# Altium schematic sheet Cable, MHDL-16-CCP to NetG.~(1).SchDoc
size B
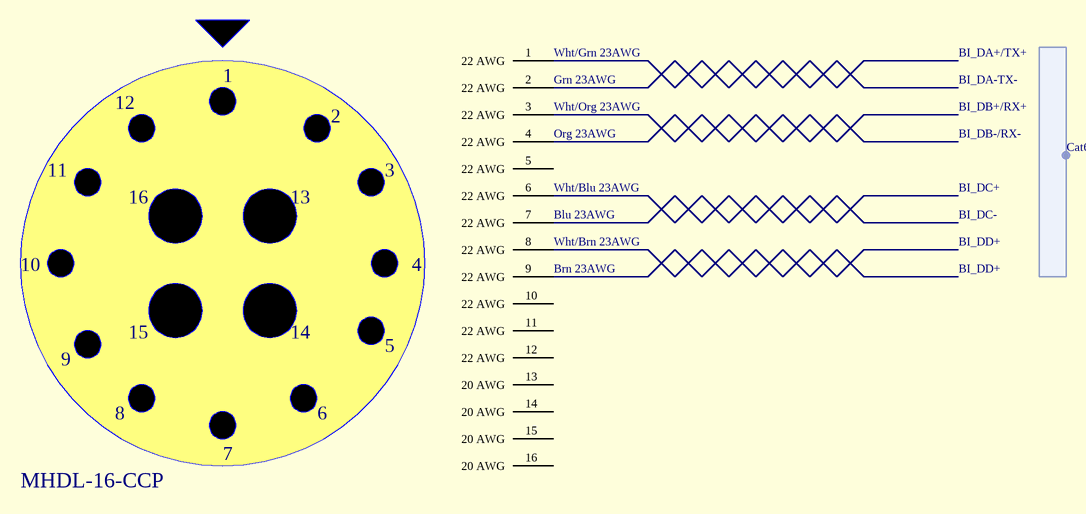
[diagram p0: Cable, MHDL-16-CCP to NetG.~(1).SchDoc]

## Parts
J?  MHDL-16-CCP

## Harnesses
Cat6E wired to TIA/EIA 568A Standard: 

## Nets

Not connected (* = marked no-connect by the designer): J? 1(22_AWG) 2(22_AWG) 3(22_AWG) 4(22_AWG) 5(22_AWG) 6(22_AWG) 7(22_AWG) 8(22_AWG) 9(22_AWG) 10(22_AWG) 11(22_AWG) 12(22_AWG) 13(20_AWG) 14(20_AWG) 15(20_AWG) 16(20_AWG)

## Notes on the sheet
- (near J?) Wht/Grn 23AWG
- BI_DA+/TX+
- (near J?) Grn 23AWG
- (near J?) Wht/Org 23AWG
- BI_DA-TX-
- BI_DB+/RX+
- (near J?) Org 23AWG
- (near J?) Wht/Blu 23AWG
- BI_DB-/RX-
- BI_DC+
- (near J?) Blu 23AWG
- (near J?) Wht/Brn 23AWG
- BI_DC-
- BI_DD+
- (near J?) Brn 23AWG

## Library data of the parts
J? = MHDL-16-CCP-SOLDER: Impulse MHDL 16 CCP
